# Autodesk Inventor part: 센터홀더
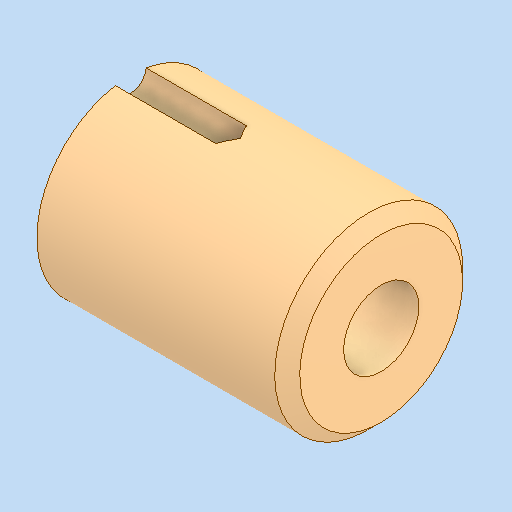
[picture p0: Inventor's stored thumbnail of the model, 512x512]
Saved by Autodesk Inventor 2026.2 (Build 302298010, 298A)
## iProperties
Created: 2026-08
Part Number: 센터홀더
Material: 강철, 연강
Document SubType Name: Modeling
Designer: PC2-02
Density: 7.86 g/cm^3
Appearance: 기본값
Author: jhkim
Sending System: Autodesk Inventor 2027
Preprocessor: ST-DEVELOPER v20.1
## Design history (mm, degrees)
feature "솔리드1"
node "솔리드2"
